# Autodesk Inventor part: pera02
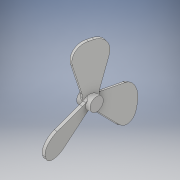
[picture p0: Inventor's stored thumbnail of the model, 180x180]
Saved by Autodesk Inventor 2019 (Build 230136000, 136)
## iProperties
Created: 2020-08
Part Number: pera02
Material: 一般
Document SubType Name: Modeling
Designer: kikut
Density: 1 g/cm^3
Appearance: 既定
Author: kikut
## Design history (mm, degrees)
sketch "スケッチ3"
  geometry: L1 (0.001, 0.01)-(-0.005, -0.009); L2 (-0.005, -0.009)-(-0.001, -0.01); L3 (-0.001, -0.01)-(0.005, 0.009); L4 (0.005, 0.009)-(0.001, 0.01); L5 (0.001, 0.01)-(-0.001, -0.01); L6 (-0.005, -0.009)-(0.005, 0.009); L7 (0, -0.014)-(0, 0.014) reference; 3 further points
  constraints: 12 end point, 3 midpoint, 2 parallel, 1 coincident, 1 perpendicular
  dimensions: "d8" = 0.02 distance of L1.start L1.end; "d9" = 165 deg angle of L7 L1; "d19" = 0.004 distance of L3.end L1.start
extrude "押し出し1" new body sketch "スケッチ3" distance "d10" = 0.079; taper "d11" = 0 deg
sketch "スケッチ6"
  geometry: L1 (-0.02, 0)-(-0.02, 0.079) reference; L2 (-0.02, 0.01)-(-0.04, 0.079); L3 (-0.04, 0.079)-(0.02, 0.079); L4 (0.02, 0.079)-(0, 0.01); L5 (0, 0)-(0, 0.079) reference; L6 (-0.02, 0.01)-(0, 0.01); L7 (-0.02, 0)-(0, 0) reference; 1 further point
  constraints: 8 end point, 2 perpendicular, 2 point on line
  dimensions: "d20" = 0.01 distance between parallel lines of L6 L7; "d21" = 0.06 distance of L2.end L3.end; "d22" = 0.02 distance from line of L2.end L1
extrude "押し出し3" join sketch "スケッチ6" distance "d23" = 0.004; taper "d24" = 0 deg
fillet "フィレット2" dims "d25" = 0.02
fillet "フィレット3" dims "d26" = 0.02
pattern_circular "円形状パターン2" dims "d28" = 360 deg
sketch "スケッチ7"
  geometry: L1 (0, 0)-(0, 0.009) reference; C1 r 0.01 at (0, 0)
  constraints: 1 centre point, 1 coincident
  dimensions: "d30" = 0.02 diameter of C1
extrude "押し出し4" join sketch "スケッチ7" stored distance "d31" = 0.02; taper "d32" = 0 deg
node "ソリッド1"
